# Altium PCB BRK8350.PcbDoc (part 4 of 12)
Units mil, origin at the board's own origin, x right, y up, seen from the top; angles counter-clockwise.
Board outline 9448.82 x 5905.51 mil, 8 copper layers (L1-TOP, L2-GND, L3-SIG, L4-GND, L5-PWR, L6-PWR, L7-GND, L8-BOT), stack 57.69 mil thick; 288 components, 543 nets, 1891 pads, 2032 vias.
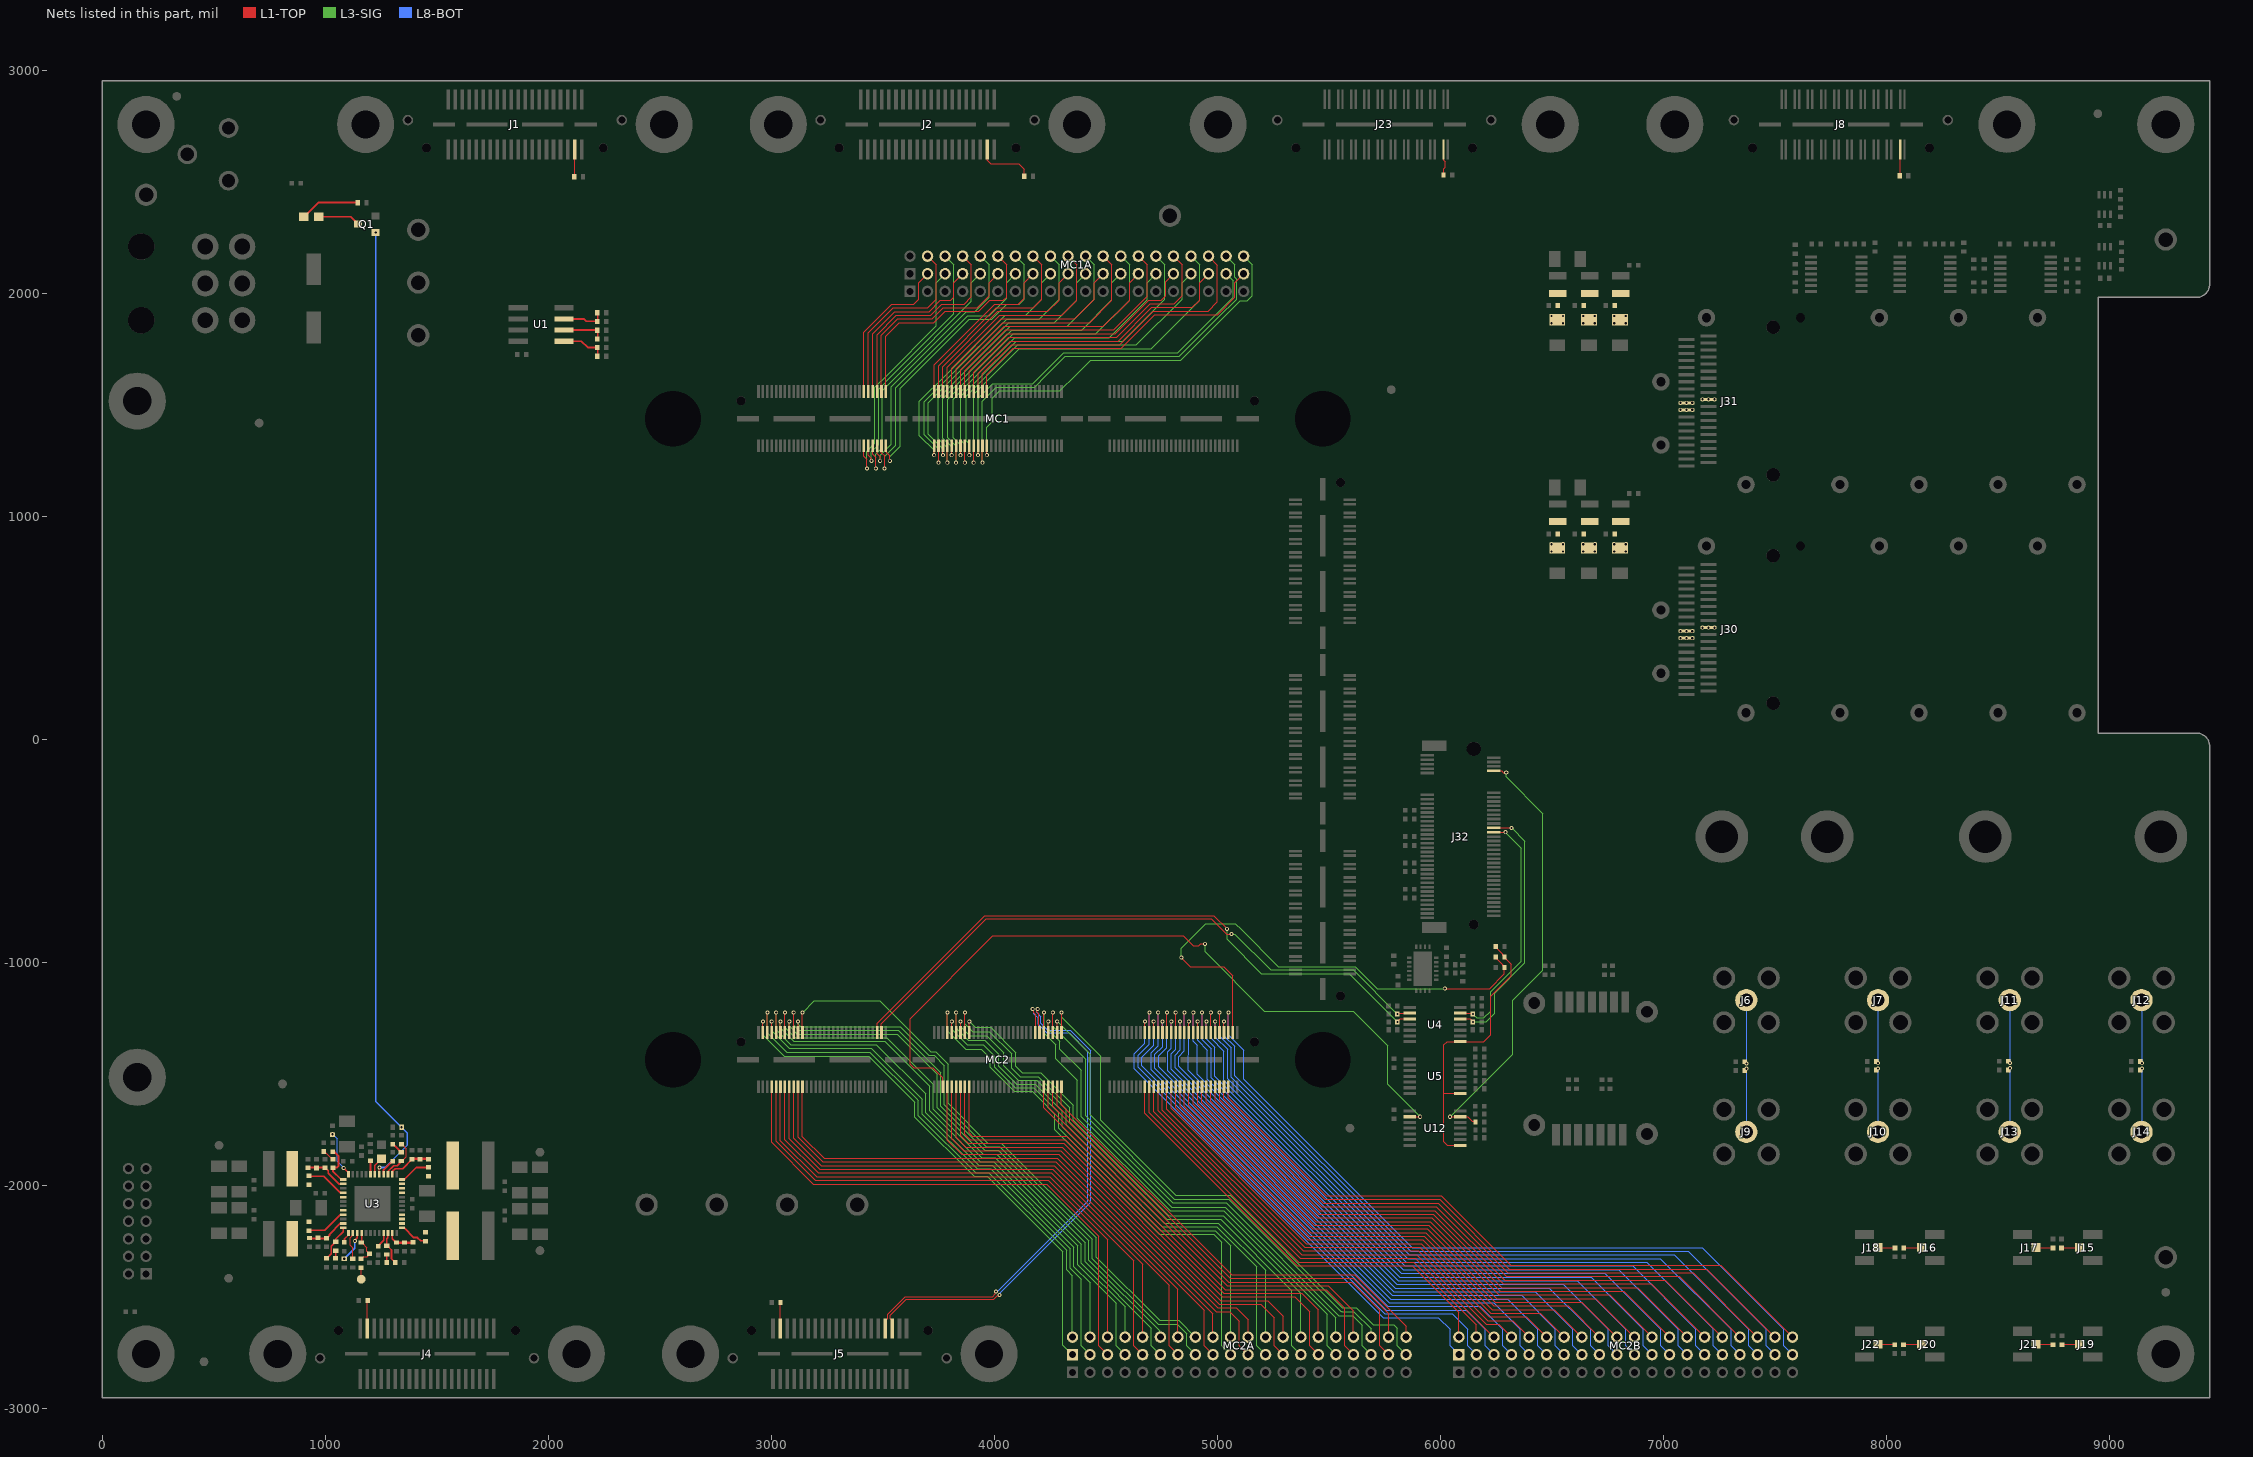
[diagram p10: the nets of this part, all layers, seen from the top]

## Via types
v1: diameter 18, hole 10, L1-TOP to L8-BOT, tented both sides, 2032 vias

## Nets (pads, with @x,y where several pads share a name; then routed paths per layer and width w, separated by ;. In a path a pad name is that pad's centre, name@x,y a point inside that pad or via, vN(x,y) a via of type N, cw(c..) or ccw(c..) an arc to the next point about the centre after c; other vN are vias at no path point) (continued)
M2_SMB_CLK: MC2.57 R32.1 U4.2 | length 2782.1
  L1-TOP w5: MC2.57@3494.11,-1315.34 3494.11,-1275.13 3963.04,-806.21 4973.16,-806.21 5041.59,-874.63 5062.37,-874.63 v1(5062.99,-874.02) ; v1(5807.09,-1232.28) 5811.02,-1228.35 U4.2@5863.19,-1228.35
  L3-SIG w5: v1(5062.99,-874.02) 5078.74,-874.02 5239.41,-1034.68 5609.49,-1034.68 v1(5807.09,-1232.28)
M2_SMB_CLK_1V8: J32.40 R35.1 U4.13 | length 1099.1
  L1-TOP w5: U4.13@6089.57,-1228.35 6141.73,-1228.35 v1(6145.67,-1232.28) ; J32.40@6239.17,-417.32 v1(6291.58,-417.32)
  L3-SIG w5: v1(6145.67,-1232.28) 6163.39,-1250 6195.37,-1250 6225.33,-1220.04 6225.33,-1133.58 6363.29,-995.61 6363.29,-489.03 v1(6291.58,-417.32)
M2_SMB_DATA: MC2.55 R33.1 U4.3 | length 2861.8
  L1-TOP w5: MC2.55@3474.43,-1315.34 3474.43,-1273.61 3956.82,-791.21 4984.12,-791.21 v1(5043.31,-850.39) ; v1(5807.09,-1267.72) 5807.09,-1265.75 5818.9,-1253.94 U4.3@5863.19,-1253.94
  L3-SIG w5: v1(5043.31,-850.39) 5043.31,-896.87 5197.61,-1051.18 5279.53,-1051.18 5590.55,-1051.18 v1(5807.09,-1267.72)
M2_SMB_DATA_1V8: J32.42 R36.1 U4.12 | length 1169.2
  L1-TOP w5: U4.12@6089.57,-1253.94 6133.86,-1253.94 6145.67,-1265.75 v1(6145.67,-1267.72) ; J32.42@6239.17,-397.64 6319.23,-397.64 v1(6319.34,-397.74)
  L3-SIG w5: v1(6145.67,-1267.72) 6204.53,-1267.72 6243.28,-1228.97 6243.28,-1138.25 6379.29,-1002.24 6379.29,-457.7 v1(6319.34,-397.74)
M2_SUSCLK: MC2.66 U12.2 | length 3370.2
  L1-TOP w5: MC2.66@3769.7,-1558.65 3769.7,-1518.61 3725.02,-1473.94 3639.29,-1473.94 3622.05,-1456.69 3622.05,-1253.26 3994.1,-881.21 4848.03,-881.21 4892.97,-926.14 4916.38,-926.14 4925.2,-917.32 v1(4944.88,-917.32) ; U12.2@5863.19,-1692.91 v1(5909.45,-1692.91)
  L3-SIG w5: v1(4944.88,-917.32) 4944.88,-952.79 5211.07,-1218.98 5608.48,-1218.98 5764.52,-1375.02 5764.52,-1547.99 v1(5909.45,-1692.91)
M2_SUSCLK_3V3: J32.68 R55.1 U12.13 | length 1966.9
  L1-TOP w5: v1(6043.31,-1692.91) U12.13@6089.57,-1692.91 6122.13,-1692.91 6142.15,-1712.94 6153.88,-1712.94 R55.1@6157.48,-1716.54 ; J32.68@6239.17,-141.73 6274.35,-141.73 6282.23,-149.61 v1(6295.28,-149.61)
  L3-SIG w5: v1(6043.31,-1692.91) 6323.28,-1412.94 6323.28,-1171.39 6459.29,-1035.38 6459.29,-333.31 6295.28,-169.29 v1(6295.28,-149.61)
M2_THREESTATE#: R64.1 R65.2 U4.8 U5.8 U12.8 | length 1281.7
  L1-TOP w5: U12.8@6089.57,-1820.87 6031.5,-1820.87 6015.75,-1805.12 6015.75,-1590.55 ; U5.8@6089.57,-1588.58 6017.72,-1588.58 6015.75,-1590.55 ; R64.1@6248.03,-929.13 6254.87,-935.98 6254.87,-939.62 6280.56,-965.31 6280.56,-969.54 R65.2@6287.4,-976.38 6287.4,-978.35 6318.28,-1009.23 6318.28,-1060.39 6225.72,-1152.96 6225.72,-1325.46 6194.88,-1356.3 U4.8@6089.57,-1356.3 6030.51,-1356.3 6015.75,-1371.06 6015.75,-1590.55
M2_THREESTATE_N_IO: MC2.177 R65.1 R66.2 | length 2294.8
  L1-TOP w5: v1(4838.58,-979.32) 4879.51,-1020.25 5028.12,-1020.25 5068.91,-1061.04 5068.91,-1240.16 MC2.177@5068.91,-1315.34 ; v1(6019.69,-1118.11) 6220.47,-1118.11 6287.4,-1051.18 R66.2@6287.4,-1023.62 6280.56,-1016.78 6280.56,-1012.39 6254.87,-986.7 6254.87,-983.22 R65.1@6248.03,-976.38
  L3-SIG w5: v1(4838.58,-979.32) 4838.58,-937.01 4948.82,-826.77 5080.55,-826.77 5106.3,-852.52 5273.47,-1019.68 5279.53,-1019.68 5618.08,-1019.68 5669.29,-1070.89 5716.51,-1118.11 v1(6019.69,-1118.11)
MC1A_3: MC1.49 MC1A.3 | length 703.5
  L1-TOP w4.5: MC1.49@3415.37,1558.68 3415.37,1824.82 3540.39,1949.83 3638.27,1949.83 3660.88,1972.44 3660.88,2046.71 MC1A.3@3700.79,2086.61
MC1A_4: MC1.51 MC1A.4 | length 839.5
  L1-TOP w4.5: MC1.51@3435.06,1558.68 3435.06,1614.17 3435.06,1821.17 3547.22,1933.33 3701.05,1933.33 3740.16,1972.44 3740.16,2125.98 MC1A.4@3700.79,2165.35
MC1A_5: MC1.50 MC1A.5 | length 1126.1
  L1-TOP w4.5: MC1.50@3415.37,1315.37 3415.37,1269.28 3429.13,1255.52 v1(3429.13,1213.35)
  L3-SIG w4.6: v1(3429.13,1213.35) 3429.13,1262.21 3429.13,1291.34 3464.46,1326.66 3464.46,1576.66 3521.65,1633.86 3740.17,1852.38 3740.17,1972.44 3740.17,2047.26 MC1A.5@3779.53,2086.61
MC1A_6: MC1.52 MC1A.6 | length 1158.9
  L1-TOP w4.5: MC1.52@3435.06,1315.37 3435.06,1272.93 3448.82,1259.16 v1(3448.82,1248.03)
  L3-SIG w4.6: v1(3448.82,1248.03) 3448.82,1262.21 3448.82,1287.55 3481.06,1319.78 3481.06,1569.78 3545.13,1633.86 3817.57,1906.3 3817.57,1972.44 3817.57,2127.31 MC1A.6@3779.53,2165.35
MC1A_7: MC1.53 MC1A.7 | length 812.4
  L1-TOP w4.5: MC1.53@3454.74,1558.68 3454.74,1614.17 3454.74,1817.52 3554.06,1916.83 3707.89,1916.83 3758.51,1967.46 3804.87,1967.46 3809.86,1972.44 3818.9,1981.48 3818.9,2047.24 MC1A.7@3858.27,2086.61
MC1A_8: MC1.55 MC1A.8 | length 946.6
  L1-TOP w4.5: MC1.55@3474.43,1558.68 3474.43,1614.17 3474.43,1813.87 3560.89,1900.33 3714.72,1900.33 3765.34,1950.96 3864.75,1950.96 3897.64,1983.84 3897.64,2125.98 MC1A.8@3858.27,2165.35
MC1A_9: MC1.54 MC1A.9 | length 1175
  L1-TOP w4.5: MC1.54@3454.74,1315.37 3454.74,1277.03 3468.5,1263.27 v1(3468.5,1213.35)
  L3-SIG w4.6: v1(3468.5,1213.35) 3468.5,1262.21 3468.5,1276.55 3497.62,1305.67 3497.62,1562.87 3568.61,1633.86 3897.64,1962.89 3897.64,1972.44 3897.64,2047.24 MC1A.9@3937.01,2086.61
MC1A_10: MC1.56 MC1A.10 | length 1231
  L1-TOP w4.5: MC1.56@3474.43,1315.37 3474.43,1280.68 3488.19,1266.92 v1(3488.19,1248.03)
  L3-SIG w4.6: v1(3488.19,1248.03) 3488.19,1262.21 3488.19,1272.62 3538.29,1322.72 3538.29,1580.07 3592.08,1633.86 3873.84,1915.62 3911.54,1915.62 3961.34,1965.42 3968.36,1972.44 3976.38,1980.46 3976.38,2125.98 MC1A.10@3937.01,2165.35
MC1A_11: MC1.57 MC1A.11 | length 922.5
  L1-TOP w4.5: MC1.57@3494.11,1558.68 3494.11,1614.17 3494.11,1810.22 3567.72,1883.83 3721.55,1883.83 3772.18,1934.46 3923.06,1934.46 3961.04,1972.44 3976.38,1987.77 3976.38,2047.24 MC1A.11@4015.75,2086.61
MC1A_12: MC1.59 MC1A.12 | length 1061.4
  L1-TOP w4.5: MC1.59@3513.8,1558.68 3513.8,1614.17 3513.8,1806.57 3574.56,1867.33 3728.39,1867.33 3779.01,1917.96 3929.9,1917.96 3979.59,1967.65 4040.48,1967.65 4045.28,1972.44 4055.12,1982.28 4055.12,2125.98 MC1A.12@4015.75,2165.35
MC1A_13: MC1.58 MC1A.13 | length 1280.8
  L1-TOP w4.5: MC1.58@3494.11,1315.37 3494.11,1284.33 3507.89,1270.55 v1(3507.89,1213.36)
  L3-SIG w4.6: v1(3507.89,1213.36) 3507.89,1262.21 3507.89,1268.84 3557.75,1318.7 3557.75,1576.05 3615.56,1633.86 3880.72,1899.02 3977.76,1899.02 4051.18,1972.44 4055.12,1976.38 4055.12,2047.24 MC1A.13@4094.49,2086.61
MC1A_14: MC1.60 MC1A.14 | length 1349.3
  L1-TOP w4.5: MC1.60@3513.8,1315.37 3517.2,1311.97 3517.2,1284.58 3531.5,1270.28 v1(3531.5,1248.03)
  L3-SIG w4.6: v1(3531.5,1248.03) 3531.5,1262.21 3531.5,1266.8 3578.74,1314.04 3578.74,1573.57 3639.03,1633.86 3887.59,1882.42 3988.72,1882.42 4055.83,1949.53 4110.95,1949.53 4133.86,1972.44 4133.86,2125.98 MC1A.14@4094.49,2165.35
MC1A_15: MC1.61 MC1A.15 | length 772.3
  L1-TOP w4.5: MC1.61@3730.33,1558.68 3730.33,1614.17 3730.33,1633.86 3730.33,1677.94 4002.85,1950.46 4106.84,1950.46 4128.82,1972.44 4133.86,1977.48 4133.86,2047.24 MC1A.15@4173.23,2086.61
MC1A_16: MC1.63 MC1A.16 | length 910.9
  L1-TOP w4.5: MC1.63@3750.02,1558.68 3750.02,1614.17 3750.02,1633.86 3750.02,1674.29 4009.69,1933.96 4174.12,1933.96 4212.6,1972.44 4212.6,2125.98 MC1A.16@4173.23,2165.35
MC1A_17: MC1.62 MC1A.17 | length 1179.5
  L1-TOP w4.5: v1(3730.36,1273.34) MC1.62@3730.33,1315.37
  L3-SIG w4.6: v1(3730.36,1273.34) 3730.36,1294.72 3663.9,1361.18 3663.9,1514.29 3783.46,1633.86 4049.88,1900.27 4140.43,1900.27 4212.6,1972.44 4212.6,2047.24 MC1A.17@4251.97,2086.61
MC1A_18: MC1.64 MC1A.18 | length 1376.9
  L1-TOP w4.5: v1(3749.83,1239.72) 3749.91,1239.8 3749.91,1315.33 MC1.64@3750.02,1315.37
  L3-SIG w4.6: v1@3749.83,1244.09 3749.83,1262.21 3749.83,1298.73 3684.88,1363.68 3684.88,1511.8 3806.94,1633.86 4056.76,1883.67 4202.57,1883.67 4291.34,1972.44 4291.34,2125.98 MC1A.18@4251.97,2165.35
MC1A_19: MC1.65 MC1A.19 | length 891.4
  L1-TOP w4.5: MC1.65@3769.7,1558.68 3769.7,1614.17 3769.7,1633.86 3769.7,1670.64 4016.52,1917.46 4240.3,1917.46 4291.34,1968.5 4291.34,1972.44 4291.34,2047.24 MC1A.19@4330.71,2086.61
MC1A_20: MC1.67 MC1A.20 | length 1027.1
  L1-TOP w4.5: MC1.67@3789.39,1558.68 3789.39,1614.17 3789.39,1633.86 3789.39,1666.99 4023.36,1900.96 4302.54,1900.96 4370.08,1968.5 4370.08,2125.98 MC1A.20@4330.71,2165.35
MC1A_21: MC1.66 MC1A.21 | length 1294.3
  L1-TOP w4.5: v1(3769.73,1273.34) MC1.66@3769.7,1315.37
  L3-SIG w4.6: v1(3769.73,1273.34) 3769.73,1302.3 3704.72,1367.31 3704.72,1508.17 3830.42,1633.86 4063.63,1867.07 4268.65,1867.07 4370.08,1968.5 4370.08,2047.24 MC1A.21@4409.45,2086.61
MC1A_22: MC1.68 MC1A.22 | length 1471
  L1-TOP w4.5: v1(3789.2,1239.72) 3789.28,1239.8 3789.28,1315.33 MC1.68@3789.35,1315.4
  L3-SIG w4.6: v1@3789.2,1244.09 3789.2,1262.21 3789.2,1306.31 3748.56,1346.95 3748.56,1528.53 3853.89,1633.86 4070.51,1850.47 4327.84,1850.47 4448.82,1971.46 4448.82,2125.98 MC1A.22@4409.45,2165.35
MC1A_23: MC1.69 MC1A.23 | length 1002.9
  L1-TOP w4.5: MC1.69@3809.07,1558.68 3809.07,1614.17 3809.07,1633.86 3809.07,1663.34 4030.19,1884.46 4360.84,1884.46 4448.82,1972.44 4448.82,2047.24 MC1A.23@4488.19,2086.61
MC1A_24: MC1.71 MC1A.24 | length 1140.9
  L1-TOP w4.5: MC1.71@3828.76,1558.68 3828.76,1614.17 3828.76,1633.86 3828.76,1659.69 4037.02,1867.96 4427.02,1867.96 4527.56,1968.5 4527.56,2125.98 MC1A.24@4488.19,2165.35
MC1A_25: MC1.70 MC1A.25 | length 1386.4
  L1-TOP w4.5: v1(3809.1,1273.34) MC1.70@3809.07,1315.37
  L3-SIG w4.6: v1(3809.1,1273.34) 3809.1,1309.88 3769.39,1349.59 3769.39,1525.88 3877.37,1633.86 4077.38,1833.87 4391.94,1833.87 4527.56,1969.49 4527.56,2047.24 MC1A.25@4566.93,2086.61
MC1A_26: MC1.72 MC1A.26 | length 1583.5
  L1-TOP w4.5: v1(3828.57,1239.72) 3828.65,1239.8 3828.65,1315.33 MC1.72@3828.76,1315.37
  L3-SIG w4.6: v1@3828.57,1244.09 3828.57,1262.21 3828.57,1313.89 3791.34,1351.12 3791.34,1524.35 3900.84,1633.86 4084.26,1817.27 4455.07,1817.27 4606.3,1968.5 4606.3,2125.98 MC1A.26@4566.93,2165.35
MC1A_27: MC1.73 MC1A.27 | length 1119.1
  L1-TOP w4.5: MC1.73@3848.44,1558.68 3848.44,1614.17 3848.44,1633.86 3848.44,1656.04 4043.86,1851.46 4489.26,1851.46 4606.3,1968.5 4606.3,2047.24 MC1A.27@4645.67,2086.61
MC1A_28: MC1.75 MC1A.28 | length 1245.2
  L1-TOP w4.5: MC1.75@3868.13,1558.68 3868.13,1614.17 3868.13,1633.86 3868.13,1652.39 4050.69,1834.96 4535.32,1834.96 4685.04,1984.68 4685.04,2125.98 MC1A.28@4645.67,2165.35
MC1A_29: MC1.74 MC1A.29 | length 1495
  L1-TOP w4.5: v1@3848.44,1273.37 MC1.74@3848.44,1315.37
  L3-SIG w4.6: v1(3848.47,1273.34) 3848.47,1317.47 3814.96,1350.98 3814.96,1524.5 3924.32,1633.86 4091.14,1800.67 4516.22,1800.67 4685.04,1969.49 4685.04,2047.24 MC1A.29@4724.41,2086.61
MC1A_30: MC1.76 MC1A.30 | length 1679.2
  L1-TOP w4.5: v1(3867.94,1239.72) 3868.02,1239.8 3868.02,1315.33 MC1.76@3868.13,1315.37
  L3-SIG w4.6: v1@3867.94,1244.09 3867.94,1262.21 3867.94,1321.47 3850.39,1339.02 3850.39,1536.46 3947.8,1633.86 4098.01,1784.07 4576.43,1784.07 4763.78,1971.42 4763.78,2125.98 MC1A.30@4724.41,2165.35
MC1A_31: MC1.77 MC1A.31 | length 1223.7
  L1-TOP w4.5: MC1.77@3887.81,1558.68 3887.81,1614.17 3887.81,1633.86 3887.81,1648.46 4057.82,1818.46 4542.15,1818.46 4692.32,1968.63 4748.5,1968.63 4767.72,1987.85 4767.72,2051.18 MC1A.31@4803.15,2086.61
MC1A_32: MC1.79 MC1A.32 | length 1356.9
  L1-TOP w4.5: MC1.79@3907.5,1558.68 3907.5,1614.17 3907.5,1633.86 3907.5,1644.81 4064.65,1801.96 4548.99,1801.96 4699.16,1952.13 4806.46,1952.13 4842.52,1988.19 4842.52,2125.98 MC1A.32@4803.15,2165.35
MC1A_33: MC1.78 MC1A.33 | length 1590.3
  L1-TOP w4.5: v1(3887.84,1273.34) MC1.78@3887.81,1315.37
  L3-SIG w4.6: v1(3887.84,1273.34) 3887.84,1325.05 3874.02,1338.87 3874.02,1536.31 3971.56,1633.86 4105.18,1767.47 4637.34,1767.47 4842.52,1972.66 4842.52,2047.24 MC1A.33@4881.89,2086.61
MC1A_34: MC1.80 MC1A.34 | length 1779.4
  L1-TOP w4.5: v1(3907.31,1239.72) 3907.39,1239.8 3907.39,1315.33 MC1.80@3907.46,1315.4
  L3-SIG w4.6: v1@3907.31,1244.09 3907.31,1262.21 3907.31,1545.4 3995.77,1633.86 4112.79,1750.87 4703.63,1750.87 4921.26,1968.5 4921.26,2125.98 MC1A.34@4881.89,2165.35
MC1A_35: MC1.81 MC1A.35 | length 1346.6
  L1-TOP w4.5: MC1.81@3927.18,1558.68 3927.18,1633.86 3927.18,1641.16 4071.13,1785.11 4555.47,1785.11 4705.99,1935.63 4888.39,1935.63 4921.26,1968.5 4921.26,2047.24 MC1A.35@4960.63,2086.61
MC1A_36: MC1.83 MC1A.36 | length 1487.2
  L1-TOP w4.5: MC1.83@3946.87,1558.68 3946.87,1637.51 4077.97,1768.61 4562.3,1768.61 4712.83,1919.13 4958.5,1919.13 5000.43,1961.06 5000.43,2125.56 MC1A.36@4960.63,2165.35
MC1A_37: MC1.82 MC1A.37 | length 1747.7
  L1-TOP w4.5: v1(3927.21,1273.34) MC1.82@3927.18,1315.37
  L3-SIG w4.6: v1(3927.21,1273.34) 3927.21,1528.97 3992.73,1594.49 4173.02,1594.49 4212.39,1633.86 4310.82,1732.28 4822.83,1732.28 5070.87,1980.31 5070.87,2055.12 MC1A.37@5039.37,2086.61
MC1A_38: MC1.84 MC1A.38 | length 1889.5
  L1-TOP w4.5: v1(3946.68,1239.72) 3946.76,1239.8 MC1.84@3946.76,1315.33
  L3-SIG w4.6: v1@3946.68,1244.09 3946.68,1262.21 3946.68,1515.57 4009.43,1578.31 4180.33,1578.31 4235.87,1633.86 4317.7,1715.68 4829.71,1715.68 5006.88,1892.85 5007.02,1892.85 5087.47,1973.29 5087.47,2061.99 5078.74,2070.72 5078.74,2125.98 MC1A.38@5039.37,2165.35
MC1A_39: MC1.85 MC1A.39 | length 1453.5
  L1-TOP w4.5: MC1.85@3966.55,1558.68 3966.55,1633.86 4084.8,1752.11 4569.13,1752.11 4719.66,1902.63 5001.06,1902.63 5078.74,1980.32 5078.74,2047.24 MC1A.39@5118.11,2086.61
MC1A_40: MC1.86 MC1A.40 | length 1857.1
  L1-TOP w4.5: v1@3966.55,1273.37 MC1.86@3966.55,1315.37
  L3-SIG w4.6: v1(3966.58,1273.34) 3966.58,1397.69 3991.14,1422.24 3991.14,1527.7 4024.66,1561.21 4294.48,1561.21 4367.13,1633.86 4431.65,1698.38 4835.89,1698.38 5013.75,1876.25 5013.9,1876.25 5102.71,1965.06 5134.35,1965.06 5157.48,1988.19 5157.48,2125.98 MC1A.40@5118.11,2165.35
MC2A_1: MC2.3 MC2A.1 | length 2375.6
  L1-TOP w4.5: MC2.3@2962.61,-1315.34 2962.61,-1265.84 v1(2962.71,-1265.74)
  L3-SIG w4.6: v1@2962.51,-1265.74 2962.51,-1324.72 3058.74,-1420.95 3437.32,-1420.95 3628.18,-1611.8 3643.44,-1627.06 3643.44,-1694.62 3909.16,-1960.34 3969.23,-1960.34 4307.09,-2298.19 4307.09,-2716.54 MC2A.1@4350.39,-2759.84
MC2A_2: MC2.5 MC2A.2 | length 2366.2
  L1-TOP w4.5: MC2.5@2982.36,-1315.27 2982.36,-1225.79 v1(2982.53,-1225.62)
  L3-SIG w4.6: v1@2982.41,-1225.62 2982.41,-1316.75 3068.3,-1402.64 3442.5,-1402.64 3651.66,-1611.8 3660.04,-1620.18 3660.04,-1687.74 3916.03,-1943.74 3976.11,-1943.74 4323.69,-2291.31 4323.69,-2378.51 4350.39,-2405.22 MC2A.2@4350.39,-2681.1
MC2A_3: MC2.7 MC2A.3 | length 2385.6
  L1-TOP w4.5: MC2.7@3001.98,-1315.34 3001.98,-1265.84 v1(3002.08,-1265.74)
  L3-SIG w4.6: v1@3001.88,-1265.74 3001.88,-1307.02 3079.92,-1385.06 3447.68,-1385.06 3674.43,-1611.8 3676.64,-1614.01 3676.64,-1680.87 3922.91,-1927.14 3982.99,-1927.14 4340.29,-2284.44 4340.29,-2371.64 4389.76,-2421.11 4389.76,-2720.47 MC2A.3@4429.13,-2759.84
MC2A_4: MC2.9 MC2A.4 | length 2388.7
  L1-TOP w4.5: MC2.9@3021.73,-1315.27 3021.73,-1225.79 v1(3021.9,-1225.62)
  L3-SIG w4.6: v1@3021.78,-1225.62 3021.78,-1303.97 3087.13,-1369.31 3471.79,-1369.31 3693.34,-1590.86 3693.34,-1611.8 3693.34,-1673.95 3929.83,-1910.43 3989.9,-1910.43 4356.99,-2277.52 4356.99,-2364.86 4429.13,-2437.01 MC2A.4@4429.13,-2681.1
MC2A_5: MC2.8 MC2A.5 | length 2437.4
  L1-TOP w4.5: MC2.8@3001.98,-1558.65 3001.98,-1611.8 3001.98,-1807.35 3189.07,-1994.43 4234.59,-1994.43 4468.5,-2228.35 4468.5,-2720.47 MC2A.5@4507.87,-2759.84
MC2A_6: MC2.10 MC2A.6 | length 2350.5
  L1-TOP w4.5: MC2.10@3021.67,-1558.65 3021.67,-1611.8 3021.67,-1803.41 3196.19,-1977.93 4241.71,-1977.93 4507.87,-2244.09 MC2A.6@4507.87,-2681.1
MC2A_7: MC2.11 MC2A.7 | length 2457.8
  L1-TOP w4.5: MC2.11@3041.35,-1315.34 3041.35,-1265.84 v1(3041.45,-1265.74)
  L3-SIG w4.6: v1@3041.25,-1265.74 3041.25,-1294.14 3100.67,-1353.56 3508.21,-1353.56 3710.04,-1555.39 3710.04,-1611.8 3710.04,-1667.03 3936.75,-1893.73 3996.82,-1893.73 4373.69,-2270.6 4373.69,-2356.21 4547.24,-2529.76 4547.24,-2720.47 MC2A.7@4586.61,-2759.84
MC2A_8: MC2.13 MC2A.8 | length 2452.4
  L1-TOP w4.5: MC2.13@3061.2,-1315.17 3061.2,-1225.69 v1(3061.37,-1225.52)
  L3-SIG w4.6: v1@3061.15,-1225.52 3061.15,-1290.56 3108.4,-1337.81 3518.1,-1337.81 3726.64,-1546.35 3726.64,-1611.8 3726.64,-1660.15 3943.62,-1877.13 4003.7,-1877.13 4390.29,-2263.72 4390.29,-2349.34 4586.61,-2545.66 MC2A.8@4586.61,-2681.1
MC2A_9: MC2.12 MC2A.9 | length 2486.5
  L1-TOP w4.5: MC2.12@3041.35,-1558.65 3041.35,-1611.8 3041.35,-1799.76 3203.03,-1961.43 4248.83,-1961.43 4625.98,-2338.58 4625.98,-2720.47 MC2A.9@4665.35,-2759.84
MC2A_10: MC2.14 MC2A.10 | length 2399.6
  L1-TOP w4.5: MC2.14@3061.04,-1558.65 3061.04,-1611.8 3061.04,-1796.11 3209.86,-1944.93 4255.67,-1944.93 4665.35,-2354.62 MC2A.10@4665.35,-2681.1
MC2A_11: MC2.15 MC2A.11 | length 2529.5
  L1-TOP w4.5: MC2.15@3080.72,-1315.34 3080.72,-1265.84 v1(3080.82,-1265.74)
  L3-SIG w4.6: v1@3080.62,-1265.74 3080.62,-1285.97 3117.37,-1322.72 3563.81,-1322.72 3743.24,-1502.16 3743.24,-1611.8 3743.24,-1653.28 3950.5,-1860.53 4010.58,-1860.53 4406.89,-2256.85 4406.89,-2342.46 4704.72,-2640.29 4704.72,-2720.47 MC2A.11@4744.09,-2759.84
MC2A_12: MC2.17 MC2A.12 | length 2522.4
  L1-TOP w4.5: MC2.17@3100.48,-1315.27 3100.48,-1225.79 v1(3100.64,-1225.62)
  L3-SIG w4.6: v1@3100.52,-1225.62 3100.52,-1282.4 3124.25,-1306.12 3570.25,-1306.12 3759.84,-1495.71 3759.84,-1611.8 3759.84,-1646.4 3957.37,-1843.93 4017.45,-1843.93 4423.49,-2249.97 4423.49,-2335.58 4741.12,-2653.21 4741.12,-2678.13 MC2A.12@4744.09,-2681.1
MC2A_13: MC2.16 MC2A.13 | length 2535.4
  L1-TOP w4.5: MC2.16@3080.72,-1558.65 3080.72,-1611.8 3080.72,-1792.46 3216.7,-1928.43 4262.5,-1928.43 4783.46,-2449.39 4783.46,-2720.47 MC2A.13@4822.83,-2759.84
MC2A_14: MC2.18 MC2A.14 | length 2448.5
  L1-TOP w4.5: MC2.18@3100.41,-1558.65 3100.41,-1611.8 3100.41,-1788.81 3223.53,-1911.93 4269.34,-1911.93 4822.83,-2465.43 MC2A.14@4822.83,-2681.1
MC2A_15: MC2.19 MC2A.15 | length 2643
  L1-TOP w4.5: MC2.19@3120.09,-1315.34 3120.09,-1265.84 v1(3120.19,-1265.74)
  L3-SIG w4.6: v1@3119.99,-1265.74 3119.99,-1278.39 3131.12,-1289.52 3578.75,-1289.52 3707.08,-1417.86 3730.58,-1417.86 3776.44,-1463.72 3776.44,-1639.52 3964.25,-1827.33 4024.33,-1827.33 4440.09,-2243.1 4440.09,-2328.71 4734.28,-2622.9 4819.9,-2622.9 4862.2,-2665.21 4862.2,-2720.47 MC2A.15@4901.57,-2759.84
MC2A_16: MC2.21 MC2A.16 | length 2649.8
  L1-TOP w4.5: MC2.21@3139.94,-1315.17 3139.94,-1225.69 v1(3140.11,-1225.52)
  L3-SIG w4.6: v1(3140.11,-1225.52) 3192.4,-1173.23 3486.41,-1173.23 3553.34,-1240.16 3715.29,-1402.11 3737,-1402.11 3793.04,-1458.15 3793.04,-1611.8 3793.04,-1632.65 3971.12,-1810.73 4031.2,-1810.73 4456.69,-2236.22 4456.69,-2321.83 4741.16,-2606.3 4826.77,-2606.3 MC2A.16@4901.57,-2681.1
MC2A_17: MC2.20 MC2A.17 | length 2584.3
  L1-TOP w4.5: MC2.20@3120.09,-1558.65 3120.09,-1611.8 3120.09,-1785.16 3230.37,-1895.43 4276.17,-1895.43 4940.94,-2560.21 4940.94,-2720.47 MC2A.17@4980.32,-2759.84
MC2A_18: MC2.22 MC2A.18 | length 2497.5
  L1-TOP w4.5: MC2.22@3139.78,-1558.65 3139.78,-1611.8 3139.78,-1781.51 3237.2,-1878.93 4283.01,-1878.93 4980.32,-2576.24 MC2A.18@4980.32,-2681.1
MC2A_19: MC2.67 MC2A.19 | length 2380.1
  L1-TOP w4.5: MC2.67@3789.55,-1315.17 3789.55,-1225.69 v1(3789.72,-1225.52)
  L3-SIG w4.6: v1(3789.72,-1225.52) 3789.72,-1240.16 3789.72,-1306.42 3873.06,-1389.76 3940.97,-1389.76 3981.62,-1430.42 3981.62,-1471.67 4088.7,-1578.74 4169.74,-1578.74 4202.81,-1611.8 4271.65,-1680.65 4271.65,-1751.97 4739.38,-2219.69 4983.47,-2219.69 5019.68,-2255.91 5019.68,-2720.47 MC2A.19@5059.06,-2759.84
MC2A_20: MC2.69 MC2A.20 | length 2216.2
  L1-TOP w4.5: MC2.69@3809.17,-1315.24 3809.17,-1265.74 v1(3809.27,-1265.64)
  L3-SIG w4.6: v1@3809.07,-1265.64 3809.07,-1299.52 3879.63,-1370.08 3949.66,-1370.08 4001.04,-1421.46 4001.04,-1470.6 4093.44,-1562.99 4177.17,-1562.99 4288.25,-1674.08 4288.25,-1745.09 4746.25,-2203.09 4990.77,-2203.09 5059.06,-2271.37 MC2A.20@5059.06,-2681.1
MC2A_21: MC2.68 MC2A.21 | length 2050.8
  L1-TOP w4.5: MC2.68@3789.39,-1558.65 3789.39,-1611.8 3789.39,-1798.16 3853.25,-1862.03 4289.44,-1862.03 4993.98,-2566.57 5054.76,-2566.57 5098.43,-2610.24 5098.43,-2720.47 MC2A.21@5137.8,-2759.84
MC2A_22: MC2.70 MC2A.22 | length 1976.2
  L1-TOP w4.5: MC2.70@3809.07,-1558.65 3809.07,-1611.8 3809.07,-1791.47 3863.13,-1845.53 4297.71,-1845.53 5002.26,-2550.07 5085.51,-2550.07 5137.8,-2602.36 MC2A.22@5137.8,-2681.1
MC2A_23: MC2.71 MC2A.23 | length 2434.4
  L1-TOP w4.5: MC2.71@3828.92,-1315.17 3828.92,-1225.69 v1(3829.09,-1225.52)
  L3-SIG w4.6: v1@3828.76,-1225.52 3828.76,-1240.16 3828.76,-1295.01 3884.14,-1350.39 3957.23,-1350.39 4020.29,-1413.46 4020.29,-1467.03 4099.65,-1546.39 4184.04,-1546.39 4304.85,-1667.2 4304.85,-1738.22 4753.13,-2186.49 4997.52,-2186.49 4997.65,-2186.49 5075.66,-2264.5 5075.66,-2264.63 5177.17,-2366.14 5177.17,-2720.47 MC2A.23@5216.54,-2759.84
MC2A_24: MC2.73 MC2A.24 | length 2268.1
  L1-TOP w4.5: MC2.73@3848.54,-1315.24 3848.54,-1265.74 v1(3848.64,-1265.64)
  L3-SIG w4.6: v1@3848.44,-1265.64 3848.44,-1289.35 3889.17,-1330.08 3966.24,-1330.08 4041.87,-1405.71 4041.87,-1464.34 4107.32,-1529.79 4190.92,-1529.79 4321.45,-1660.33 4321.45,-1729.1 4762.25,-2169.89 5004.39,-2169.89 5004.91,-2169.89 5216.54,-2381.51 MC2A.24@5216.54,-2681.1
MC2A_25: MC2.72 MC2A.25 | length 2170.3
  L1-TOP w4.5: MC2.72@3828.76,-1558.65 3828.76,-1611.8 3828.76,-1784.79 3873,-1829.03 4304.54,-1829.03 5009.09,-2533.57 5194.99,-2533.57 5255.91,-2594.49 5255.91,-2720.47 MC2A.25@5295.28,-2759.84
MC2A_26: MC2.74 MC2A.26 | length 2095.4
  L1-TOP w4.5: MC2.74@3848.44,-1558.65 3848.44,-1611.8 3848.44,-1777.71 3883.26,-1812.53 4311.38,-1812.53 5015.92,-2517.07 5225.74,-2517.07 5295.28,-2586.61 MC2A.26@5295.28,-2681.1
MC2A_27: MC2.75 MC2A.27 | length 2480.8
  L1-TOP w4.5: MC2.75@3868.29,-1315.17 3868.29,-1225.69 v1(3868.46,-1225.52)
  L3-SIG w4.6: v1@3868.13,-1225.52 3868.13,-1240.16 3868.13,-1275.84 3904.12,-1311.83 3977.74,-1311.83 4077.38,-1411.48 4077.38,-1475.3 4115.28,-1513.19 4197.79,-1513.19 4338.05,-1653.45 4338.05,-1717.3 4774.05,-2153.29 5015.64,-2153.29 5334.65,-2472.29 5334.65,-2720.47 MC2A.27@5374.02,-2759.84
MC2A_28: MC2.77 MC2A.28 | length 2312.7
  L1-TOP w4.5: MC2.77@3887.91,-1315.24 3887.91,-1265.74 v1(3888.01,-1265.64)
  L3-SIG w4.6: v1@3887.81,-1265.64 3914.57,-1292.39 3983.25,-1292.39 4097.07,-1406.21 4097.07,-1467.14 4125.98,-1496.06 4208.98,-1496.06 4354.65,-1641.73 4354.65,-1708.98 4782.36,-2136.69 5026.63,-2136.69 5374.02,-2484.07 MC2A.28@5374.02,-2681.1
MC2A_29: MC2.76 MC2A.29 | length 2297.2
  L1-TOP w4.5: MC2.76@3868.13,-1558.65 3868.13,-1611.8 3868.13,-1772.2 3891.95,-1796.03 4318.21,-1796.03 5022.76,-2500.57 5347.03,-2500.57 5413.39,-2566.93 5413.39,-2720.47 MC2A.29@5452.76,-2759.84
MC2A_30: MC2.78 MC2A.30 | length 2222.7
  L1-TOP w4.5: MC2.78@3887.81,-1558.65 3887.81,-1611.8 3887.81,-1765.76 3901.57,-1779.53 4325.05,-1779.53 5029.59,-2484.07 5377.78,-2484.07 5452.49,-2558.79 5452.49,-2680.84 MC2A.30@5452.76,-2681.1
MC2A_31: MC2.111 MC2A.31 | length 2307
  L1-TOP w4.5: MC2.111@4222.62,-1315.17 4222.62,-1225.69 v1(4222.79,-1225.52)
  L3-SIG w4.6: v1(4222.79,-1225.52) 4222.79,-1240.16 4222.79,-1318.25 4274.39,-1369.86 4274.39,-1431.87 4372.65,-1530.13 4372.65,-1611.8 4372.65,-1699.42 4788.22,-2114.99 5028.66,-2114.99 5492.13,-2578.46 5492.13,-2720.47 MC2A.31@5531.5,-2759.84
MC2A_32: MC2.113 MC2A.32 | length 2140.2
  L1-TOP w4.5: MC2.113@4242.14,-1315.34 4242.24,-1315.24 4242.24,-1265.74 v1(4242.34,-1265.64)
  L3-SIG w4.6: v1(4242.34,-1265.64) 4242.34,-1301.32 4294.33,-1353.31 4294.33,-1389.27 4389.25,-1484.19 4389.25,-1611.8 4389.25,-1692.55 4795.1,-2098.39 5035.68,-2098.39 5531.5,-2594.21 MC2A.32@5531.5,-2681.1
MC2A_33: MC2.112 MC2A.33 | length 2040.1
  L1-TOP w4.5: MC2.112@4222.46,-1558.65 4222.46,-1653.6 4284.06,-1715.21 5036.43,-2467.57 5487.26,-2467.57 5570.87,-2551.18 5570.87,-2720.47 MC2A.33@5610.24,-2759.84
MC2A_34: MC2.114 MC2A.34 | length 1955.7
  L1-TOP w4.5: MC2.114@4242.14,-1558.65 4242.14,-1649.95 4290.9,-1698.71 5043.26,-2451.07 5498.32,-2451.07 5610.24,-2562.99 MC2A.34@5610.24,-2681.1
MC2A_35: MC2.115 MC2A.35 | length 2392.2
  L1-TOP w4.5: MC2.115@4261.83,-1315.34 4261.99,-1315.17 4261.99,-1225.69 v1(4262.16,-1225.52)
  L3-SIG w4.6: v1(4262.16,-1225.52) 4262.16,-1240.16 4262.16,-1288.24 4409.45,-1435.53 4409.45,-1611.8 4409.45,-1688.98 4799.62,-2079.15 5039.91,-2079.15 5545.04,-2584.28 5606.5,-2584.28 5606.6,-2584.18 5649.61,-2627.18 5649.61,-2720.47 MC2A.35@5688.98,-2759.84
MC2A_36: MC2.117 MC2A.36 | length 2225
  L1-TOP w4.5: MC2.117@4281.51,-1315.34 4281.61,-1315.24 4281.61,-1265.74 v1(4281.71,-1265.64)
  L3-SIG w4.6: v1(4281.71,-1265.64) 4429.13,-1413.06 4429.13,-1611.8 4429.13,-1685.04 4806.64,-2062.55 5050.38,-2062.55 5552.86,-2565.02 5557.1,-2565.02 5558.45,-2566.37 5612.27,-2566.37 5688.98,-2643.08 MC2A.36@5688.98,-2681.1
MC2A_37: MC2.116 MC2A.37 | length 2148.5
  L1-TOP w4.5: MC2.116@4261.83,-1558.65 4261.83,-1646.3 4297.73,-1682.21 5050.1,-2434.57 5602.47,-2434.57 5728.35,-2560.45 5728.35,-2720.47 MC2A.37@5767.72,-2759.84
MC2A_38: MC2.118 MC2A.38 | length 2061.6
  L1-TOP w4.5: MC2.118@4281.51,-1558.65 4281.51,-1642.66 4304.57,-1665.71 5056.93,-2418.07 5609.31,-2418.07 5767.72,-2576.48 MC2A.38@5767.72,-2681.1
MC2A_39: MC2.119 MC2A.39 | length 2497.2
  L1-TOP w4.5: MC2.119@4301.2,-1315.34 4301.36,-1315.17 4301.36,-1225.69 v1(4301.53,-1225.52)
  L3-SIG w4.6: v1(4301.53,-1225.52) 4301.53,-1240.16 4301.53,-1247.15 4476.38,-1422 4476.38,-1611.8 4476.38,-1708.81 4813.52,-2045.95 5057.26,-2045.95 5559.74,-2548.42 5623.65,-2548.42 5699.78,-2624.56 5789.91,-2624.56 5807.09,-2641.73 5807.09,-2720.47 MC2A.39@5846.46,-2759.84
MC2A_40: MC2.120 MC2A.40 | length 2086.1
  L1-TOP w4.5: MC2.120@4301.2,-1558.65 4301.2,-1639.01 4311.4,-1649.21 5063.77,-2401.57 5616.14,-2401.57 5846.46,-2631.89 MC2A.40@5846.46,-2681.1
MC2B_1: MC2.137 MC2B.1 | length 2310.6
  L1-TOP w4.5: MC2.137@4675.21,-1315.34 4675.31,-1315.24 4675.31,-1265.74 v1(4675.41,-1265.64)
  L8-BOT w4.5: v1(4675.41,-1265.64) 4675.41,-1364.37 4628.42,-1411.36 4628.42,-1477.86 5743.58,-2593.03 5990.66,-2593.03 6043.31,-2645.67 6043.31,-2720.47 MC2B.1@6082.68,-2759.84
MC2B_2: MC2.138 MC2B.2 | length 2007
  L1-TOP w4.5: MC2.138@4675.21,-1558.65 4675.21,-1677.62 5358.33,-2360.74 5873.13,-2360.74 6082.68,-2570.29 MC2B.2@6082.68,-2681.1
MC2B_3: MC2.139 MC2B.3 | length 2450.5
  L1-TOP w4.5: MC2.139@4694.9,-1315.34 4695.06,-1315.17 4695.06,-1225.69 v1(4695.23,-1225.52)
  L8-BOT w4.5: v1(4695.23,-1225.52) 4695.23,-1367.88 4644.92,-1418.19 4644.92,-1471.03 5750.42,-2576.53 6052.91,-2576.53 6122.05,-2645.67 6122.05,-2720.47 MC2B.3@6161.42,-2759.84
MC2B_4: MC2.140 MC2B.4 | length 2031.5
  L1-TOP w4.5: MC2.140@4694.9,-1558.65 4694.9,-1673.97 5365.17,-2344.24 5879.97,-2344.24 6161.42,-2625.7 MC2B.4@6161.42,-2681.1
MC2B_5: MC2.141 MC2B.5 | length 2429.5
  L1-TOP w4.5: MC2.141@4714.58,-1315.34 4714.68,-1315.24 4714.68,-1265.74 v1(4714.78,-1265.64)
  L8-BOT w4.5: v1(4714.78,-1265.64) 4714.78,-1371.66 4661.42,-1425.03 4661.42,-1464.19 5757.25,-2560.03 6114.93,-2560.03 6200.79,-2645.89 6200.79,-2720.47 MC2B.5@6240.16,-2759.84
MC2B_6: MC2.142 MC2B.6 | length 2055.9
  L1-TOP w4.5: MC2.142@4714.58,-1558.65 4714.58,-1670.32 5372,-2327.74 5886.8,-2327.74 MC2B.6@6240.16,-2681.1
MC2B_7: MC2.143 MC2B.7 | length 2548.1
  L1-TOP w4.5: MC2.143@4734.27,-1315.34 4734.43,-1315.17 4734.43,-1225.69 v1(4734.6,-1225.52)
  L8-BOT w4.5: v1(4734.6,-1225.52) 4734.6,-1375.18 4703.87,-1405.91 4703.87,-1483.31 5764.09,-2543.53 6177.39,-2543.53 6279.53,-2645.67 6279.53,-2720.47 MC2B.7@6318.9,-2759.84
MC2B_8: MC2.144 MC2B.8 | length 2112.8
  L1-TOP w4.5: MC2.144@4734.27,-1558.65 4734.27,-1666.68 5378.84,-2311.24 5893.63,-2311.24 6205.94,-2623.55 6261.35,-2623.55 MC2B.8@6318.9,-2681.1
MC2B_9: MC2.145 MC2B.9 | length 2527.3
  L1-TOP w4.5: MC2.145@4753.95,-1315.34 4754.05,-1315.24 4754.05,-1265.74 v1(4754.15,-1265.64)
  L8-BOT w4.5: v1(4754.15,-1265.64) 4754.15,-1378.96 4720.37,-1412.74 4720.37,-1476.47 5770.92,-2527.03 6239.63,-2527.03 6358.27,-2645.67 6358.27,-2720.47 MC2B.9@6397.64,-2759.84
MC2B_10: MC2.146 MC2B.10 | length 2169.8
  L1-TOP w4.5: MC2.146@4753.95,-1558.65 4753.95,-1663.03 5385.67,-2294.74 5900.47,-2294.74 6212.78,-2607.05 6323.59,-2607.05 MC2B.10@6397.64,-2681.1
MC2B_11: MC2.147 MC2B.11 | length 2667.2
  L1-TOP w4.5: MC2.147@4773.64,-1315.34 4773.8,-1315.17 4773.8,-1225.69 v1(4773.97,-1225.52)
  L8-BOT w4.5: v1(4773.97,-1225.52) 4773.97,-1382.48 4736.87,-1419.58 4736.87,-1469.64 5777.76,-2510.53 6301.87,-2510.53 6437.01,-2645.67 6437.01,-2720.47 MC2B.11@6476.38,-2759.84
MC2B_12: MC2.148 MC2B.12 | length 2226.7
  L1-TOP w4.5: MC2.148@4773.64,-1558.65 4773.64,-1659.38 5392.51,-2278.24 5907.3,-2278.24 6219.61,-2590.55 6385.83,-2590.55 MC2B.12@6476.38,-2681.1
MC2B_13: MC2.149 MC2B.13 | length 2626.6
  L1-TOP w4.5: MC2.149@4793.32,-1315.34 4793.42,-1315.24 4793.42,-1265.74 v1(4793.52,-1265.64)
  L8-BOT w4.5: v1(4793.52,-1265.64) 4793.52,-1386.26 4777.27,-1402.51 4777.27,-1486.71 5784.59,-2494.03 6364.11,-2494.03 6515.75,-2645.67 6515.75,-2720.47 MC2B.13@6555.12,-2759.84
MC2B_14: MC2.150 MC2B.14 | length 2283.6
  L1-TOP w4.5: MC2.150@4793.32,-1558.65 4793.32,-1655.73 5399.34,-2261.74 5914.14,-2261.74 6226.44,-2574.05 6448.07,-2574.05 MC2B.14@6555.12,-2681.1
MC2B_15: MC2.151 MC2B.15 | length 2766.5
  L1-TOP w4.5: MC2.151@4813.01,-1315.34 4813.17,-1315.17 4813.17,-1225.69 v1(4813.34,-1225.52)
  L8-BOT w4.5: v1(4813.34,-1225.52) 4813.34,-1389.78 4793.77,-1409.35 4793.77,-1479.87 5791.43,-2477.53 6426.35,-2477.53 6594.49,-2645.67 6594.49,-2720.47 MC2B.15@6633.86,-2759.84
MC2B_16: MC2.152 MC2B.16 | length 2340.5
  L1-TOP w4.5: MC2.152@4813.01,-1558.65 4813.01,-1652.08 5406.17,-2245.24 5920.97,-2245.24 6233.28,-2557.55 6510.31,-2557.55 MC2B.16@6633.86,-2681.1
MC2B_17: MC2.153 MC2B.17 | length 2745.7
  L1-TOP w4.5: MC2.153@4832.69,-1315.34 4832.79,-1315.24 4832.79,-1265.74 v1(4832.89,-1265.64)
  L8-BOT w4.5: v1(4832.89,-1265.64) 4832.89,-1393.56 4810.27,-1416.18 4810.27,-1473.04 5798.26,-2461.03 6488.59,-2461.03 6673.23,-2645.67 6673.23,-2720.47 MC2B.17@6712.6,-2759.84
MC2B_18: MC2.154 MC2B.18 | length 2397.4
  L1-TOP w4.5: MC2.154@4832.69,-1558.65 4832.69,-1648.43 5413.01,-2228.74 5927.81,-2228.74 6240.11,-2541.05 6572.55,-2541.05 MC2B.18@6712.6,-2681.1
MC2B_19: MC2.155 MC2B.19 | length 2885
  L1-TOP w4.5: MC2.155@4852.38,-1315.34 4852.54,-1315.17 4852.54,-1225.69 v1(4852.71,-1225.52)
  L8-BOT w4.5: v1(4852.71,-1225.52) 4852.71,-1397.08 4826.77,-1423.01 4826.77,-1466.2 5805.1,-2444.53 6549.75,-2444.53 6751.97,-2646.75 6751.97,-2720.47 MC2B.19@6791.34,-2759.84
MC2B_20: MC2.156 MC2B.20 | length 2454.4
  L1-TOP w4.5: MC2.156@4852.38,-1558.65 4852.38,-1644.78 5074.49,-1866.89 5419.84,-2212.24 5934.64,-2212.24 6246.95,-2524.55 6634.79,-2524.55 MC2B.20@6791.34,-2681.1
MC2B_21: MC2.157 MC2B.21 | length 2843.6
  L1-TOP w4.5: MC2.157@4872.06,-1315.34 4872.16,-1315.24 4872.16,-1265.74 v1(4872.26,-1265.64)
  L8-BOT w4.5: v1(4872.26,-1265.64) 4872.26,-1415.14 4868.92,-1418.48 4868.92,-1485.02 5811.93,-2428.03 6613.07,-2428.03 6830.71,-2645.67 6830.71,-2720.47 MC2B.21@6870.08,-2759.84
MC2B_22: MC2.158 MC2B.22 | length 2511.3
  L1-TOP w4.5: MC2.158@4872.06,-1558.65 4872.06,-1641.13 5426.68,-2195.74 5941.48,-2195.74 6253.78,-2508.05 6697.03,-2508.05 MC2B.22@6870.08,-2681.1
MC2B_23: MC2.159 MC2B.23 | length 2978
  L1-TOP w4.5: MC2.159@4891.75,-1315.34 4891.91,-1315.17 4891.91,-1225.69 v1(4892.08,-1225.52)
  L8-BOT w4.5: v1(4892.08,-1225.52) 4892.08,-1354.34 4909.45,-1371.72 4909.45,-1502.21 5818.76,-2411.53 6675.31,-2411.53 6909.45,-2645.67 6909.45,-2720.47 MC2B.23@6948.82,-2759.84
MC2B_24: MC2.160 MC2B.24 | length 2568.2
  L1-TOP w4.5: MC2.160@4891.75,-1558.65 4891.75,-1637.48 4934.72,-1680.45 5433.51,-2179.24 5948.31,-2179.24 6260.62,-2491.55 6759.27,-2491.55 MC2B.24@6948.82,-2681.1
MC2B_25: MC2.161 MC2B.25 | length 2954.6
  L1-TOP w4.5: MC2.161@4911.43,-1315.34 4911.53,-1315.24 4911.53,-1265.74 v1(4911.63,-1265.64)
  L8-BOT w4.5: v1(4911.63,-1265.64) 4911.63,-1350.56 4955.19,-1394.12 4955.19,-1524.62 5825.6,-2395.03 6737.55,-2395.03 6988.19,-2645.67 6988.19,-2720.47 MC2B.25@7027.56,-2759.84
MC2B_26: MC2.162 MC2B.26 | length 2625.1
  L1-TOP w4.5: MC2.162@4911.43,-1558.65 4911.43,-1633.83 4941.95,-1664.35 5095,-1817.39 5440.35,-2162.74 5955.14,-2162.74 6267.45,-2475.05 6821.51,-2475.05 MC2B.26@7027.56,-2681.1
MC2B_27: MC2.163 MC2B.27 | length 3092.1
  L1-TOP w4.5: MC2.163@4931.12,-1315.34 4931.28,-1315.17 4931.28,-1225.69 v1(4931.45,-1225.52)
  L8-BOT w4.5: v1(4931.45,-1225.52) 4931.45,-1347.04 4947.71,-1363.31 4971.69,-1387.29 4971.69,-1517.78 5832.43,-2378.53 6800.27,-2378.53 7066.93,-2645.19 7066.93,-2720.47 MC2B.27@7106.3,-2759.84
MC2B_28: MC2.164 MC2B.28 | length 2682
  L1-TOP w4.5: MC2.164@4931.12,-1558.65 4931.12,-1630.18 5447.18,-2146.24 5961.98,-2146.24 6274.29,-2458.55 6883.75,-2458.55 MC2B.28@7106.3,-2681.1
MC2B_29: MC2.165 MC2B.29 | length 3068.5
  L1-TOP w4.5: MC2.165@4950.8,-1315.34 4950.9,-1315.24 4950.9,-1265.74 v1(4951,-1265.64)
  L8-BOT w4.5: v1(4951,-1265.64) 4951,-1343.26 4988.19,-1380.45 4988.19,-1510.95 5839.27,-2362.03 6862.03,-2362.03 7145.67,-2645.67 7145.67,-2720.47 MC2B.29@7185.04,-2759.84
MC2B_30: MC2.166 MC2B.30 | length 2738.9
  L1-TOP w4.5: MC2.166@4950.8,-1558.65 4950.8,-1626.53 5454.02,-2129.74 5968.81,-2129.74 6281.12,-2442.05 6945.99,-2442.05 MC2B.30@7185.04,-2681.1
MC2B_31: MC2.167 MC2B.31 | length 3206.5
  L1-TOP w4.5: MC2.167@4970.49,-1315.34 4970.65,-1315.17 4970.65,-1225.69 v1(4970.82,-1225.52)
  L8-BOT w4.5: v1(4970.82,-1225.52) 4970.82,-1339.75 5029.24,-1398.17 5029.24,-1528.67 5846.1,-2345.53 6925.8,-2345.53 7224.41,-2644.14 7224.41,-2720.47 MC2B.31@7263.78,-2759.84
MC2B_32: MC2.168 MC2B.32 | length 2795.9
  L1-TOP w4.5: MC2.168@4970.49,-1558.65 4970.49,-1622.88 5460.85,-2113.24 5975.65,-2113.24 6287.96,-2425.55 7008.23,-2425.55 MC2B.32@7263.78,-2681.1
MC2B_33: MC2.169 MC2B.33 | length 3182.3
  L1-TOP w4.5: MC2.169@4990.17,-1315.34 4990.27,-1315.24 4990.27,-1265.74 v1(4990.37,-1265.64)
  L8-BOT w4.5: v1(4990.37,-1265.64) 4990.37,-1335.97 5045.74,-1391.33 5045.74,-1521.83 5852.94,-2329.03 6986.51,-2329.03 7303.15,-2645.67 7303.15,-2720.47 MC2B.33@7342.52,-2759.84
MC2B_34: MC2.170 MC2B.34 | length 2852.8
  L1-TOP w4.5: MC2.170@4990.17,-1558.65 4990.17,-1619.23 5467.69,-2096.74 5982.48,-2096.74 6294.79,-2409.05 7070.47,-2409.05 MC2B.34@7342.52,-2681.1
MC2B_35: MC2.171 MC2B.35 | length 3319.5
  L1-TOP w4.5: MC2.171@5009.86,-1315.34 5010.02,-1315.17 5010.02,-1225.69 v1(5010.19,-1225.52)
  L8-BOT w4.5: v1(5010.19,-1225.52) 5010.19,-1332.45 5062.24,-1384.5 5062.24,-1515 5859.77,-2312.53 7048.75,-2312.53 7381.89,-2645.67 7381.89,-2720.47 MC2B.35@7421.26,-2759.84
MC2B_36: MC2.172 MC2B.36 | length 2909.7
  L1-TOP w4.5: MC2.172@5009.86,-1558.65 5009.86,-1615.58 5474.52,-2080.24 5989.32,-2080.24 6301.62,-2392.55 7132.71,-2392.55 MC2B.36@7421.26,-2681.1
MC2B_37: MC2.173 MC2B.37 | length 3296.1
  L1-TOP w4.5: MC2.173@5029.54,-1315.34 5029.64,-1315.24 5029.64,-1265.74 v1(5029.74,-1265.64)
  L8-BOT w4.5: v1(5029.74,-1265.64) 5029.74,-1328.67 5078.74,-1377.67 5078.74,-1508.16 5866.61,-2296.03 7110.99,-2296.03 7460.63,-2645.67 7460.63,-2720.47 MC2B.37@7500,-2759.84
MC2B_38: MC2.174 MC2B.38 | length 2966.6
  L1-TOP w4.5: MC2.174@5029.54,-1558.65 5029.54,-1611.93 5481.35,-2063.74 5996.15,-2063.74 6308.46,-2376.05 7194.95,-2376.05 MC2B.38@7500,-2681.1
MC2B_39: MC2.175 MC2B.39 | length 3433.3
  L1-TOP w4.5: MC2.175@5049.23,-1315.34 5049.39,-1315.17 5049.39,-1225.69 v1(5049.56,-1225.52)
  L8-BOT w4.5: v1(5049.56,-1225.52) 5049.56,-1325.15 5118.11,-1393.7 5118.11,-1524.2 5873.44,-2279.53 7173.23,-2279.53 7539.37,-2645.67 7539.37,-2720.47 MC2B.39@7578.74,-2759.84
MC2B_40: MC2.176 MC2B.40 | length 3023.5
  L1-TOP w4.5: MC2.176@5049.23,-1558.65 5049.23,-1608.28 5488.19,-2047.24 6002.99,-2047.24 6315.29,-2359.55 7257.19,-2359.55 MC2B.40@7578.74,-2681.1
NetC6_1: C6.1 J6.1 | length 284.5
  L8-BOT w4.2: J6.1@7371.72,-1170.11 7372.89,-1171.28 v1(7372.89,-1454.08)
NetC7_1: C7.1 J7.1 | length 299.4
  L8-BOT w4.2: J7.1@7952.24,-1181.85 J7.1@7963.98,-1170.11 ; v1(7962.27,-1452.91) J7.1@7962.27,-1170.11
NetC8_1: C8.1 J9.1 | length 288.6
  L1-TOP w4.2: J9.1@7369.98,-1756.46 ccw(c7375.92,-1756.46) J9.1@7371.72,-1760.66
  L8-BOT w4.2: J9.1@7371.72,-1760.66 7372.89,-1759.49 v1(7372.89,-1477.2)
NetC9_1: C9.1 J10.1 | length 298.9
  L8-BOT w4.2: J10.1@7952.24,-1748.92 J10.1@7963.98,-1760.66 ; J10.1@7962.27,-1758.31 v1(7962.27,-1476.02)
NetC10_1: C10.1 J11.1 | length 299.4
  L8-BOT w4.2: J11.1@8542.63,-1180.85 8554.37,-1169.11 v1(8554.37,-1451.91)
NetC11_1: C11.1 J12.1 | length 301.8
  L1-TOP w4.2: J12.1@9143.37,-1170.11 cw(c9141.23,-1172.26) J12.1@9144.26,-1172.26
  L8-BOT w4.2: J12.1@9134.26,-1181.85 9146,-1170.11 v1(9146,-1452.91)
NetC12_1: C12.1 J13.1 | length 298.9
  L8-BOT w4.2: J13.1@8542.63,-1747.92 J13.1@8554.37,-1759.66 ; J13.1@8554.37,-1757.31 v1(8554.37,-1475.02)
NetC13_1: C13.1 J14.1 | length 298.9
  L8-BOT w4.2: J14.1@9134.26,-1748.92 J14.1@9146,-1760.66 ; J14.1@9146,-1758.31 v1(9146,-1476.02)
NetC14_1: C14.1 J15.1 | length 79.9
  L1-TOP w4.2: C14.1@8785.4,-2279.27 8785.66,-2279.53 J15.1@8865.16,-2279.53
NetC15_1: C15.1 J16.1 | length 78.9
  L1-TOP w4.2: C15.1@8077.74,-2279.27 8078,-2279.53 J16.1@8156.5,-2279.53
NetC16_1: C16.1 J17.1 | length 75.9
  L1-TOP w4.2: J17.1@8670.28,-2279.53 8745.77,-2279.53 C16.1@8746.03,-2279.27
NetC17_1: C17.1 J18.1 | length 76.9
  L1-TOP w4.2: J18.1@7961.61,-2279.53 8038.11,-2279.53 C17.1@8038.37,-2279.27
NetC18_1: C18.1 J19.1 | length 78.9
  L1-TOP w4.2: C18.1@8786.4,-2712.34 8786.66,-2712.6 J19.1@8865.16,-2712.6
NetC19_1: C19.1 J20.1 | length 79.9
  L1-TOP w4.2: C19.1@8076.74,-2712.34 8077,-2712.6 J20.1@8156.5,-2712.6
NetC20_1: C20.1 J21.1 | length 76.9
  L1-TOP w4.2: J21.1@8670.28,-2712.6 8746.77,-2712.6 C20.1@8747.03,-2712.34
NetC21_1: C21.1 J22.1 | length 75.9
  L1-TOP w4.2: J22.1@7961.61,-2712.6 8037.11,-2712.6 C21.1@8037.37,-2712.34
NetC30_2: C30.2 U3.18 | length 82.1
  L1-TOP w8: U3.18@1222.58,-1950.77 1222.58,-1911.32 C30.2@1252.74,-1881.16
NetC31_2: C31.2 U3.19 | length 62.1
  L1-TOP w8: C31.2@1202.74,-1888.77 1202.74,-1950.61 U3.19@1202.9,-1950.77
NetC35_1: C35.1 U3.1 | length 129.8
  L1-TOP w8: U3.1@1344.63,-2190.93 1353.81,-2190.93 1397.47,-2234.58 1413.47,-2234.58 1427.58,-2248.69 C35.1@1450.47,-2248.69
NetC35_2: C35.2 L1.1 U3.2 U3.3 U3.4
NetC41_1: C41.1 R16.1 R17.2 U3.47 | length 125.7
  L1-TOP w6: U3.47@1301.32,-2214.55 1301.32,-2240.44 R17.2@1319.47,-2258.58
  L1-TOP w12: R17.2@1319.47,-2258.58 1319.86,-2258.19 C41.1@1393.47,-2258.19
NetC42_1: C42.1 R18.2 | length 37.6
  L1-TOP w6: C42.1@1274.85,-2345.66 1275.74,-2344.77 R18.2@1275.74,-2308.41
NetC43_1: C43.1 U3.45 | length 70
  L1-TOP w6: C43.1@1237.84,-2274.55 1237.84,-2271.12 1261.95,-2247.01 U3.45@1261.95,-2214.55
NetC44_1: C44.1 R18.1 U3.46 | length 152
  L1-TOP w6: R18.1@1275.47,-2268.39 1275.47,-2240.58 1281.64,-2234.41 U3.46@1281.64,-2214.55
  L1-TOP w8: R18.1@1275.47,-2268.39 1297.47,-2290.39 1297.47,-2329.47 C44.1@1315.47,-2347.47
NetC45_1: C45.1 U3.12 | length 140.4
  L1-TOP w8: U3.12@1344.63,-1974.39 1355.01,-1974.39 1408.85,-1920.55 C45.1@1462.74,-1920.55
NetC45_2: C45.2 L2.1 U3.9 U3.10 U3.11
NetC51_2: C51.2 U3.16 | length 77.9
  L1-TOP w8: U3.16@1261.95,-1950.77 1261.95,-1930.56 C51.2@1302.74,-1889.77
NetC52_1: C52.1 R19.1 R20.2 U3.14 | length 199.1
  L1-TOP w8: U3.14@1301.32,-1950.77 1301.32,-1938.04 1313.71,-1925.66 1347.09,-1925.66 1389.14,-1883.62 R20.2@1389.14,-1881.77
  L1-TOP w12: R20.2@1388.74,-1881.38 1462.35,-1881.38 C52.1@1462.74,-1881.77
NetC53_1: C53.1 R21.2 | length 54.9
  L1-TOP w8: C53.1@1303.27,-1814.77 1341.27,-1852.77 R21.2@1341.27,-1853.95
NetC54_1: C54.1 R21.1 U3.15 | length 185.5
  L1-TOP w5: R21.1@1341.27,-1889.38 1345.55,-1889.38 1363.27,-1871.66 1363.27,-1835.3 C54.1@1342.74,-1814.77
  L1-TOP w8: U3.15@1281.64,-1950.77 1281.64,-1937.76 1306.74,-1912.66 1322.51,-1912.66 R21.1@1341.27,-1893.91
NetC55_1: C55.1 U3.24 | length 209.2
  L1-TOP w8: v1(1082.74,-1922.66) 1104.47,-1944.39 U3.24@1104.47,-1950.77
  L8-BOT w5: v1(1033.1,-1771.19) 1053.1,-1791.19 1053.1,-1893.02 v1(1082.74,-1922.66)
NetC56_1: C56.1 U3.28 | length 183.7
  L1-TOP w8: C56.1@927.74,-1959.55 994.23,-1959.55 1068.12,-2033.45 U3.28@1080.85,-2033.45
NetC56_2: C56.2 L3.1 U3.29
NetC62_1: C62.1 R22.1 R24.2 U3.26 | length 195.3
  L1-TOP w8: R22.1@922.74,-1920.38 998.74,-1920.38 1013.74,-1935.38 1013.74,-1946.81 1061.01,-1994.08 U3.26@1080.85,-1994.08
NetC63_1: C63.1 U3.37 | length 51.5
  L1-TOP w8: C63.1@1086.74,-2258.66 1086.74,-2240.66 1104.47,-2222.93 U3.37@1104.47,-2214.55
NetC64_1: C64.1 R23.2 | length 56.8
  L1-TOP w5: C64.1@993.74,-1846.77 996.57,-1846.77 R23.2@1034.74,-1884.95
NetC65_1: C65.1 R23.1 U3.25 | length 178.7
  L1-TOP w8: C65.1@1042.74,-1847.77 1042.74,-1851.16 1059.27,-1867.69 1059.27,-1914.66 1053.55,-1920.38 1034.74,-1920.38 1034.74,-1936.66 1072.47,-1974.39 U3.25@1080.85,-1974.39
NetC66_1: C66.1 U3.33 | length 182.1
  L1-TOP w8: C66.1@927.74,-2201.77 997.63,-2201.77 1067.53,-2131.87 U3.33@1080.85,-2131.87
NetC66_2: C66.2 L4.1 U3.32
NetC70_1: C70.1 R26.1 R29.2 U3.35 | length 182.8
  L1-TOP w8: R26.1@929.74,-2238.66 930.14,-2238.27 967.74,-2238.27 1005.06,-2238.27 1005.74,-2238.95 1019.65,-2225.03 1019.65,-2219.6 1068.01,-2171.24 U3.35@1080.85,-2171.24
NetC71_1: C71.1 TP21.1 | length 51.3
  L1-TOP w5: C71.1@1160.74,-2370.24 1161.42,-2370.92 TP21.1@1161.42,-2421.26
NetC71_2: C71.2 C73.2 R28.2 U3.40 | length 161
  L1-TOP w5: C71.2@1160.74,-2332.05 1172.63,-2320.16 1187.63,-2320.16 1198.74,-2309.05 1186.74,-2297.05 1186.74,-2279.62 1165.98,-2258.87 R28.2@1161.47,-2258.87
  L1-TOP w8: R28.2@1161.47,-2258.87 1163.53,-2256.8 U3.40@1163.53,-2214.55
NetC72_1: C72.1 R27.2 | length 40
  L1-TOP w8: C72.1@1045.74,-2328.55 C72.1@1047.74,-2326.55 ; C72.1@1047.74,-2328.55 C72.1@1047.74,-2326.55 ; R27.2@1047.74,-2291.38 C72.1@1047.74,-2326.55
NetC74_1: C74.1 R27.1 U3.36 | length 168.8
  L1-TOP w8: C74.1@1005.74,-2328.66 1026.74,-2307.66 1026.74,-2273.66 1047.74,-2252.66 1047.74,-2241.16 1080.85,-2208.05 U3.36@1080.85,-2190.93
NetC90_2: C90.2 C91.2 J30.29 L6.2
  other v1: 7076.69,484.25 7103.15,484.25 7129.61,484.25 6779.1,841.09 6831.1,841.09 6779.1,874.02 6831.1,874.02
NetC92_2: C92.2 C93.2 J30.10 L7.2
  other v1: 7175.5,500 7201.97,500 7228.43,500 6497.61,841.09 6549.61,841.09 6497.61,874.02 6549.61,874.02
NetC94_2: C94.2 C95.2 J30.30 L5.2
  other v1: 7076.69,452.76 7103.15,452.76 7129.61,452.76 6640.32,841.09 6692.32,841.09 6640.32,874.02 6692.32,874.02
NetC102_2: C102.2 C103.2 J31.29 L9.2
  other v1: 7076.67,1507.87 7103.13,1507.87 7129.6,1507.87 6779.09,1864.72 6831.09,1864.72 6779.09,1897.64 6831.09,1897.64
NetC104_2: C104.2 C105.2 J31.10 L10.2
  other v1: 7175.49,1523.62 7201.95,1523.62 7228.42,1523.62 6497.59,1864.72 6549.59,1864.72 6497.59,1897.64 6549.59,1897.64
NetC106_2: C106.2 C107.2 J31.30 L8.2
  other v1: 7076.67,1476.38 7103.13,1476.38 7129.6,1476.38 6640.31,1864.72 6692.31,1864.72 6640.31,1897.64 6692.31,1897.64
NetD1_1: D1.1 Q1.3 | length 192.3
  L1-TOP w8: D1.1@970.47,2342.52 1114.09,2342.52 1133.97,2322.64 1133.97,2320.67 1145.72,2308.92 Q1.3@1147.68,2308.92
NetD1_2: D1.2 R30.1 | length 268.2
  L1-TOP w8: D1.2@903.54,2342.52 905.51,2342.52 968.5,2405.51 R30.1@1145.67,2405.51
NetJ1_4: J1.4 R1.2 | length 122
  L1-TOP w5: J1.4@2118.19,2643.11 2118.24,2521.5 R1.2@2118.51,2521.24
NetJ2_4: J2.4 R2.2 | length 261.7
  L1-TOP w5: J2.4@3968.59,2643.11 3968.59,2594.4 3984.25,2578.74 4110.24,2578.74 4133.86,2555.12 R2.2@4133.86,2523.62
NetJ4_4: J4.4 R10.2 | length 126.4
  L1-TOP w5: R10.2@1188.72,-2516.76 1188.89,-2516.93 J4.4@1188.94,-2643.11
NetJ5_4: J5.4 R9.2 | length 121.6
  L1-TOP w5: J5.4@3039.34,-2643.11 R9.2@3039.34,-2521.51
NetJ8_4: J8.4 R12.2 | length 117.3
  L1-TOP w5: R12.2@8060.78,2525.87 8061.18,2526.27 J8.4@8061.18,2643.03
NetJ23_4: J23.4 R13.2 | length 119.8
  L1-TOP w5: R13.2@6013.94,2528.87 6013.94,2558.26 6020.69,2565.01 6020.69,2578.74 6020.69,2589.25 6013.94,2596 J23.4@6013.94,2643.03
NetQ1_1: Q1.1 R31.1 U3.17 | length 4346
  L1-TOP w5: U3.17@1242.27,-1950.77 1242.27,-1922.38 v1(1244.1,-1920.55)
  L8-BOT w7: v1(1226.43,2271.52) 1226.43,-1624.06 v1(1342.52,-1740.16) 1366.99,-1764.63 1366.99,-1821.28 1267.72,-1920.55 v1(1244.1,-1920.55)
NetR3_1: R3.1 R6.2 U1.1 | length 200.7
  L1-TOP w8: U1.1@2070.42,1784.26 2148.81,1784.26 2176.81,1756.26 R6.2@2220.47,1756.26 ; R3.1@2222.44,1716.54 R6.2@2222.44,1755.54
NetR4_1: R4.1 R7.2 U1.2 | length 189.1
  L1-TOP w8: U1.2@2070.42,1834.26 R7.2@2220.47,1834.26 ; R4.1@2222.44,1794.54 R7.2@2222.44,1833.54
NetR5_1: R5.1 R8.2 U1.3 | length 193.6
  L1-TOP w8: U1.3@2070.42,1884.26 2159.05,1884.26 2170.05,1873.26 R5.1@2220.47,1873.26 ; R5.1@2222.44,1872.54 R8.2@2222.44,1911.54
NetR14_1: R14.1 U3.39 | length 139
  L1-TOP w8: v1(1132.74,-2249.66) 1132.74,-2246.66 1143.84,-2235.56 U3.39@1143.84,-2214.55
  L8-BOT w8: v1(1085.74,-2329.48) 1132.74,-2282.48 v1(1132.74,-2249.66)
NetR25_2: R25.2 U3.38 | length 126.7
  L1-TOP w5: R25.2@1123.54,-2331.45 1123.54,-2279.94 1112.1,-2268.49 1112.1,-2237.16 1113.43,-2235.83 1113.49,-2235.83 1124.16,-2225.16 U3.38@1124.16,-2214.55
PORTA_C2P_CLKN: J5.36 MC2.109 | length 2320
  L1-TOP w4.2: J5.36@3543.34,-2643.11 3543.34,-2606.36 3537.44,-2600.46 3536.35,-2600.46 3533.89,-2598 3533.89,-2583.05 3605.13,-2511.81 3997.26,-2511.81 4014.14,-2494.93 4021.14,-2494.93 v1(4023.78,-2492.29) ; v1(4194.54,-1209.61) 4192.05,-1209.61 4189.59,-1212.07 4189.59,-1221.07 4199.23,-1230.71 4199.23,-1311.8 MC2.109@4202.77,-1315.34
  L8-BOT w4.2: v1(4023.78,-2492.29) 4026.42,-2489.65 4026.42,-2482.65 4431.96,-2077.11 4431.96,-1611.8 4431.96,-1395.92 4340.19,-1304.15 4239.51,-1304.15 4209.3,-1273.94 4209.3,-1244.73 4189.59,-1225.02 4189.59,-1218.3 4194.54,-1213.35 v1(4194.54,-1209.61)
PORTA_C2P_CLKP: J5.34 MC2.107 | length 2320
  L1-TOP w4.2: J5.34@3511.84,-2643.11 3511.84,-2606.36 3517.74,-2600.46 3518.83,-2600.46 3521.29,-2598 3521.29,-2577.84 3599.91,-2499.21 3992.04,-2499.21 4005.23,-2486.02 4005.23,-2479.02 v1(4007.87,-2476.38) ; v1(4172.04,-1209.61) 4174.5,-1212.07 4176.99,-1212.07 4176.99,-1226.29 4186.63,-1235.92 4186.63,-1311.8 MC2.107@4183.09,-1315.34
  L8-BOT w4.2: v1(4007.87,-2476.38) 4010.51,-2473.74 4017.51,-2473.74 4419.36,-2071.89 4419.36,-1611.8 4419.36,-1401.14 4334.97,-1316.75 4234.29,-1316.75 4196.7,-1279.16 4196.7,-1249.95 4186.91,-1240.16 4176.99,-1230.24 4176.99,-1218.3 4172.04,-1213.35 v1(4172.04,-1209.61)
